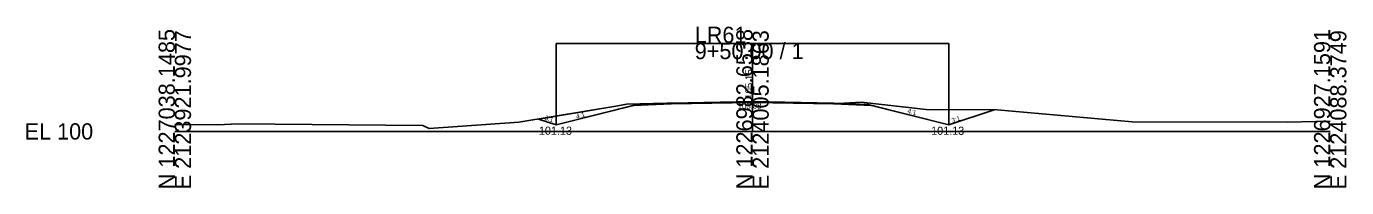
# Model space of a CAD drawing. Extents: x 2121193 to 2127979, y 1225108 to 1234639.
# Drawn here: x 2126750.9 to 2126979.4, y 1234607.5 to 1234635.3 of the extents above; entities that cross this region are included whole.
import ezdxf

# ---------------------------------------------------------------- set-up
doc = ezdxf.new("R2010")
doc.units = 0
for name, color, linetype in [('XS_CELL', 7, 'Continuous'), ('XS_M_DITCH', 7, 'Continuous'), ('XS_M_SHAPES_EARTHWORK', 7, 'Continuous'), ('XS_P_FINISHED_GRADE', 7, 'Continuous'), ('XS_P_FINISHED_GRADE_ELEV_TX', 7, 'Continuous'), ('XS_P_SUBGRADE_GRANULAR', 7, 'Continuous'), ('XS_P_SUBGRADE_PAVEMENT', 7, 'Continuous'), ('XS_P_TX_DCH', 7, 'Continuous'), ('XS_P_TX_FS_BS', 7, 'Continuous'), ('XS_X_GROUND', 7, 'Continuous'), ('XS_X_GROUND_TX', 7, 'Continuous')]:
    doc.layers.add(name, color=color, linetype=linetype)

msp = doc.modelspace()

# ---------------------------------------------------------------- linework, layer by layer
at = {"layer": 'XS_CELL'}
for p, q in [((2126876.61, 1234617.21), (2126876.61, 1234632.49)), ((2126776.61, 1234617.21), (2126876.61, 1234617.21)), ((2126876.61, 1234617.21), (2126976.61, 1234617.21))]:
    msp.add_line(p, q, dxfattribs=at)
at = {"layer": 'XS_M_DITCH'}
for p, q in [((2126842.61, 1234618.34), (2126842.61, 1234632.39)), ((2126842.61, 1234632.39), (2126910.61, 1234632.39)), ((2126910.61, 1234632.39), (2126910.61, 1234618.34))]:
    msp.add_line(p, q, dxfattribs=at)
at = {"layer": 'XS_M_SHAPES_EARTHWORK'}
for p, q in [((2126895.39, 1234622.28), (2126891.5, 1234622.04)), ((2126906.65, 1234621.01), (2126895.39, 1234622.28)), ((2126853.32, 1234621.61), (2126839.57, 1234619.35)), ((2126854.79, 1234621.91), (2126853.32, 1234621.61)), ((2126861.78, 1234622.11), (2126854.79, 1234621.91)), ((2126856.02, 1234621.69), (2126862.54, 1234621.95)), ((2126856.61, 1234621.84), (2126856.02, 1234621.69)), ((2126856.61, 1234621.84), (2126862.61, 1234622.08)), ((2126862.61, 1234622.08), (2126856.61, 1234621.84)), ((2126862.61, 1234622.12), (2126861.78, 1234622.11)), ((2126862.54, 1234621.95), (2126862.61, 1234622.08)), ((2126862.61, 1234622.08), (2126862.61, 1234622.12)), ((2126891.5, 1234622.04), (2126890.66, 1234621.99)), ((2126890.66, 1234621.99), (2126890.68, 1234621.95)), ((2126890.68, 1234621.95), (2126897.2, 1234621.69)), ((2126891.5, 1234622.04), (2126896.61, 1234621.84)), ((2126896.61, 1234621.84), (2126891.5, 1234622.04)), ((2126897.2, 1234621.69), (2126896.61, 1234621.84)), ((2126918.46, 1234620.96), (2126906.65, 1234621.01)), ((2126910.61, 1234618.34), (2126918.46, 1234620.96)), ((2126839.57, 1234619.35), (2126842.61, 1234618.34))]:
    msp.add_line(p, q, dxfattribs=at)
for points in [[(2126842.61, 1234618.34), (2126856.02, 1234621.69), (2126856.61, 1234621.84)], [(2126896.61, 1234621.84), (2126897.2, 1234621.69), (2126910.61, 1234618.34)]]:
    msp.add_lwpolyline(points, dxfattribs=at)
at = {"layer": 'XS_P_FINISHED_GRADE'}
for p, q in [((2126876.61, 1234622.36), (2126862.61, 1234622.08)), ((2126876.61, 1234622.36), (2126890.61, 1234622.08)), ((2126856.61, 1234621.84), (2126842.61, 1234618.34)), ((2126862.61, 1234622.08), (2126856.61, 1234621.84)), ((2126890.61, 1234622.08), (2126896.61, 1234621.84)), ((2126896.61, 1234621.84), (2126910.61, 1234618.34)), ((2126910.61, 1234618.34), (2126918.46, 1234620.96)), ((2126842.61, 1234618.34), (2126839.57, 1234619.35))]:
    msp.add_line(p, q, dxfattribs=at)
at = {"layer": 'XS_P_SUBGRADE_GRANULAR'}
for p, q in [((2126862.54, 1234621.95), (2126856.02, 1234621.69)), ((2126890.68, 1234621.95), (2126897.2, 1234621.69))]:
    msp.add_line(p, q, dxfattribs=at)
at = {"layer": 'XS_P_SUBGRADE_PAVEMENT'}
for p, q in [((2126876.61, 1234622.23), (2126862.54, 1234621.95)), ((2126876.61, 1234622.23), (2126890.68, 1234621.95)), ((2126862.61, 1234622.08), (2126862.54, 1234621.95)), ((2126890.61, 1234622.08), (2126890.68, 1234621.95))]:
    msp.add_line(p, q, dxfattribs=at)
at = {"layer": 'XS_X_GROUND'}
for p, q in [((2126866.95, 1234622.17), (2126876.07, 1234622.3)), ((2126876.07, 1234622.3), (2126876.61, 1234622.29)), ((2126876.61, 1234622.29), (2126881.92, 1234622.17)), ((2126890.52, 1234621.99), (2126895.39, 1234622.28)), ((2126895.39, 1234622.28), (2126906.65, 1234621.01)), ((2126836.18, 1234618.8), (2126853.32, 1234621.61)), ((2126853.32, 1234621.61), (2126854.79, 1234621.91)), ((2126854.79, 1234621.91), (2126861.78, 1234622.11)), ((2126861.78, 1234622.11), (2126866.95, 1234622.17)), ((2126881.92, 1234622.17), (2126890.52, 1234621.99)), ((2126906.65, 1234621.01), (2126918.96, 1234620.95)), ((2126918.96, 1234620.95), (2126942.34, 1234618.89)), ((2126776.61, 1234618.42), (2126783.98, 1234618.36)), ((2126783.98, 1234618.36), (2126787.58, 1234618.49)), ((2126787.58, 1234618.49), (2126819.52, 1234618.23)), ((2126819.52, 1234618.23), (2126820.61, 1234617.71)), ((2126820.61, 1234617.71), (2126836.18, 1234618.8)), ((2126942.34, 1234618.89), (2126969.18, 1234618.81)), ((2126969.18, 1234618.81), (2126976.61, 1234618.97))]:
    msp.add_line(p, q, dxfattribs=at)

# ---------------------------------------------------------------- texts
at = {"layer": 'XS_CELL'}
for s, p in [('N 1227038.1485', (2126776.61, 1234607.21)), ('E 2123921.9977', (2126779.41, 1234607.21)), ('N 1226982.6538', (2126876.61, 1234607.21)), ('E 2124005.1863', (2126879.41, 1234607.21)), ('N 1226927.1591', (2126976.61, 1234607.21)), ('E 2124088.3749', (2126979.41, 1234607.21))]:
    msp.add_text(s, height=2.8, rotation=90, dxfattribs=at).set_placement(p)
for s, p in [('LR61', (2126866.61, 1234632.49)), ('9+50.00 / 1', (2126866.61, 1234629.69)), ('EL 100', (2126750.61, 1234615.81))]:
    msp.add_text(s, height=2.8, dxfattribs=at).set_placement(p)
at = {"layer": 'XS_P_FINISHED_GRADE_ELEV_TX'}
msp.add_text(' 105.15', height=1.25, rotation=90, dxfattribs=at).set_placement((2126876.61, 1234622.36))
at = {"layer": 'XS_P_TX_DCH'}
for p in [(2126839.63, 1234616.63), (2126907.53, 1234616.62)]:
    msp.add_text('101.13', height=1.4, dxfattribs=at).set_placement(p)
at = {"layer": 'XS_P_TX_FS_BS'}
for s, rotation, p in [('3:1', 341.5651, (2126840.53, 1234619.26)), ('4:1', 14.0362, (2126846.17, 1234619.4)), ('4:1', 345.9638, (2126903.38, 1234620.4)), ('3:1', 18.4349, (2126911.21, 1234618.68))]:
    msp.add_text(s, height=0.8, rotation=rotation, dxfattribs=at).set_placement(p)
at = {"layer": 'XS_X_GROUND_TX'}
msp.add_text('105.08', height=1, dxfattribs=at).set_placement((2126874.05, 1234621.13))

doc.saveas('drawing.dxf')
